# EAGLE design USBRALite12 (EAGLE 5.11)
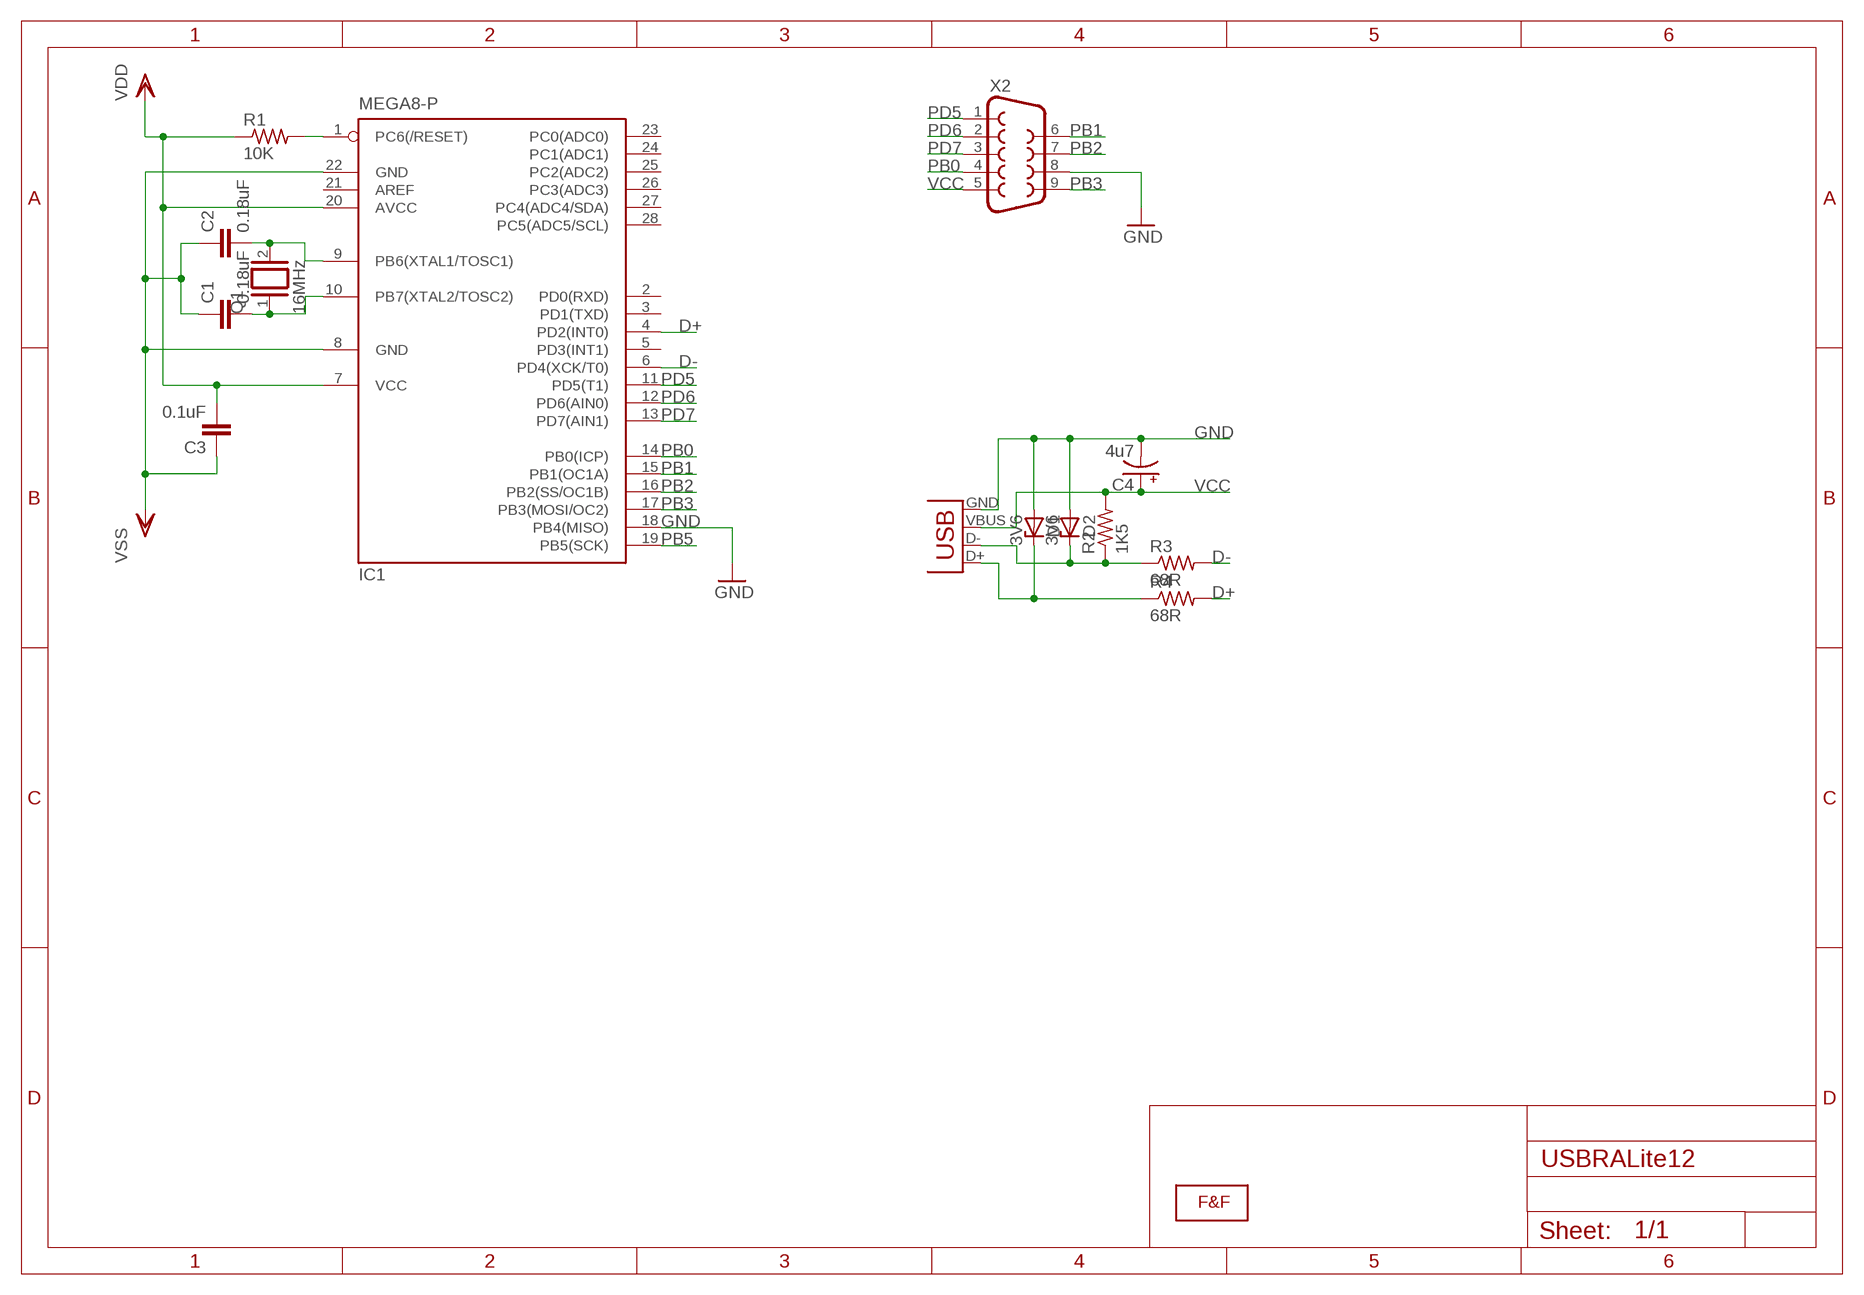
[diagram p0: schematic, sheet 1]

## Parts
C1  0.18uF  CAPPTH  [CAP-PTH-SMALL]
C2  0.18uF  CAPPTH  [CAP-PTH-SMALL]
C3  0.1uF  CAPPTH  [CAP-PTH-SMALL]
C4  4u7  CPOL-USE2.5-6  [E2,5-6]
D1  3V6  ZENER-DIODEZD-5  [ZDIO-5]
D2  3V6  ZENER-DIODEZD-5  [ZDIO-5]
IC1  MEGA8-P  [DIL28-3]
Q1  16MHz  XTAL/S  [QS]
R1  10K  R-US_0207/10  [0207/10]
R2  1K5  R-US_0207/10  [0207/10]
R3  68R  R-US_0207/10  [0207/10]
R4  68R  R-US_0207/10  [0207/10]
U$1  LOGOLOGO_WITH_SMOKE_BIG  [LOGO_BIG]
X1  USBPTH  [USB-B-PTH]
X2  DB9MALE  [DB9_MALE]

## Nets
D+: IC1.4(PD2(INT0)) R4.2
D-: IC1.6(PD4(XCK/T0)) R3.2
GND: C1.1 C2.1 C3.1 C4.- D1.A D2.A IC1.8(GND) IC1.18(PB4(MISO)) IC1.22(GND) X1.GND X2.8 ; supply symbol labelled VSS
N$1: IC1.1(PC6(/RESET)) R1.2
N$2: C2.2 IC1.9(PB6(XTAL1/TOSC1)) Q1.2
N$3: C1.2 IC1.10(PB7(XTAL2/TOSC2)) Q1.1
N$8: D1.C R4.1 X1.D+
N$9: D2.C R2.1 R3.1 X1.D-
PB0: IC1.14(PB0(ICP)) X2.4
PB1: IC1.15(PB1(OC1A)) X2.6
PB2: IC1.16(PB2(SS/OC1B)) X2.7
PB3: IC1.17(PB3(MOSI/OC2)) X2.9
PB5: IC1.19(PB5(SCK))
PD5: IC1.11(PD5(T1)) X2.1
PD6: IC1.12(PD6(AIN0)) X2.2
PD7: IC1.13(PD7(AIN1)) X2.3
VCC: C3.2 C4.+ IC1.7(VCC) IC1.20(AVCC) R1.1 R2.2 X1.VBUS X2.5 ; supply symbol labelled VDD
Unconnected: IC1.2(PD0(RXD)) IC1.3(PD1(TXD)) IC1.5(PD3(INT1)) IC1.21(AREF) IC1.23(PC0(ADC0)) IC1.24(PC1(ADC1)) IC1.25(PC2(ADC2)) IC1.26(PC3(ADC3)) IC1.27(PC4(ADC4/SDA)) IC1.28(PC5(ADC5/SCL))

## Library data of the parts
C1-C3 = SparkFun:CAP: Capacitor
C4 = adafruit:CPOL-US: POLARIZED CAPACITOR, American symbol
D1 D2 = diode:ZENER-DIODE: Z-Diode
IC1 = atmel:MEGA8-P: MICROCONTROLLER 8 Kbytes FLASH, 1 kbytes SRAM, 512 bytes EEPROM, USART, 4-channel 10 bit ADC, 2-channel 8 bit ADC Pin compatible with Atmega48, ATMega88, ATMega168 Source: avr.lbr; OC_FARNELL: unknown; OC_NEWARK: unknown
Q1 = special:XTAL/S: CRYSTAL
R1-R4 = adafruit:R-US_: RESISTOR, American symbol
U$1 = F&F:LOGO: Faísca e Fumaça Logo
X1 = SparkFun:USB: USB Connectors USB-B-PTH is fully proven SKU : PRT-00139 USB-miniB is fully proven SKU : PRT-00587 USB-A-PCB is untested. USB-A-H is throughly reviewed, but untested. Spark Fun Electronics SKU : PRT-00437 USB-B-SMT is throughly reviewed, but untested. Needs silkscreen touching up. USB-A-S has not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
X2 = SparkFun:DB9: DB9 Connector Standard DB9 (D-Sub 9) serial connector. Can be used for CAN bus as well as RS485 and RS232. Footprint production proven. Spark Fun Electronics SKU : PRT-00429

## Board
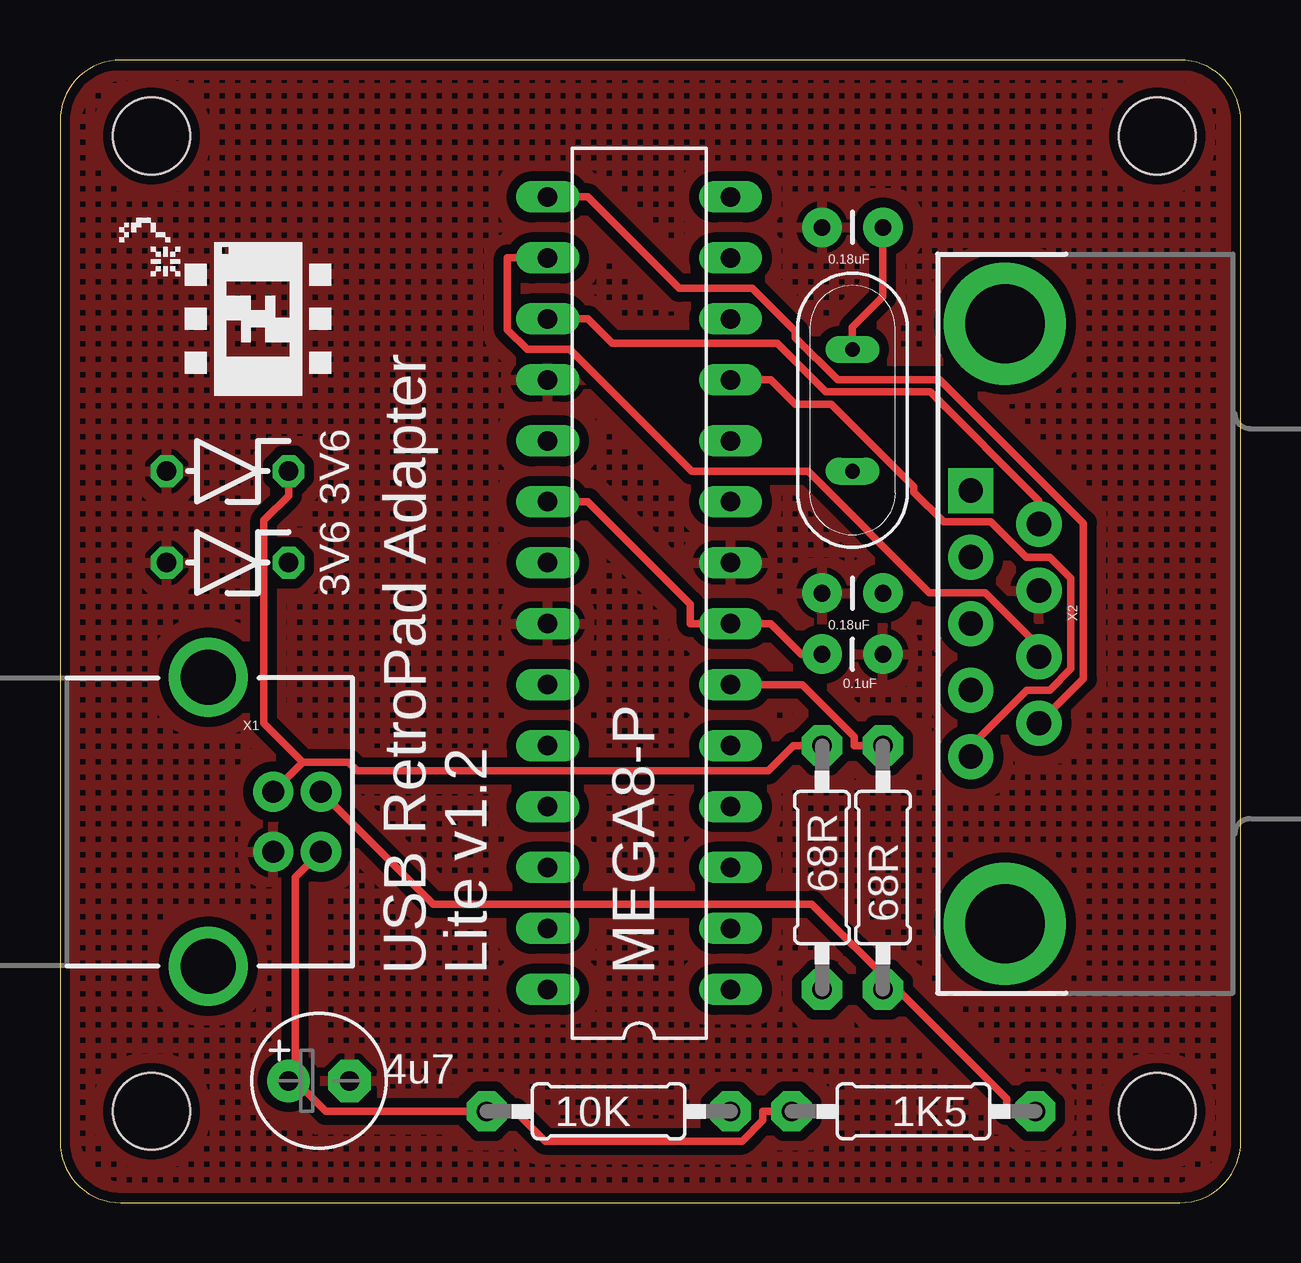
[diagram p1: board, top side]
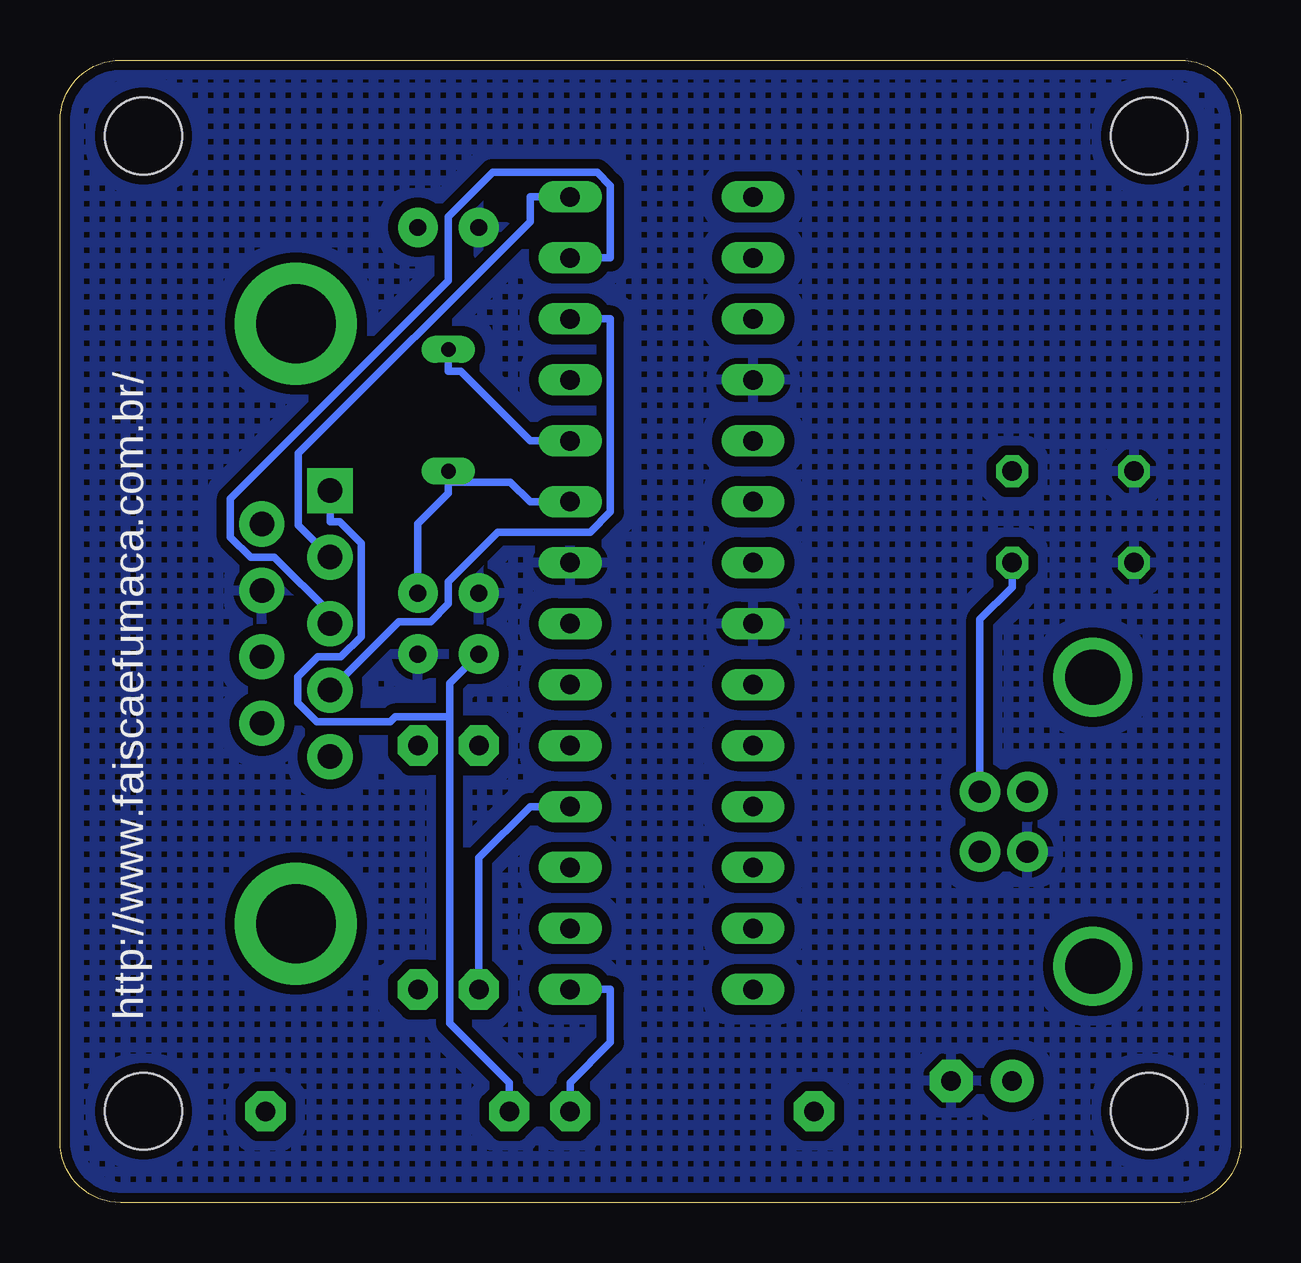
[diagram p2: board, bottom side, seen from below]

Size 49.2 x 47.62 mm. Coordinates in mm from the lower left corner, seen from the top.
Outline: 49.2,45.08 arc90 46.66,47.62 2.54,47.62 arc90 0,45.08 0,2.54 arc90 2.54,0 46.66,0 arc90 49.2,2.54 49.2,45.08
Copper layers (1*16): Top 0.035mm / dielectric 1.5mm / Bottom 0.035mm
Design rules "ITead_rule": minimum track width 6mil, minimum drill 12mil, track to track 6mil, track to pad 6mil, pad to pad 6mil, via to via 6mil, smd to smd 0mil, copper to edge 10mil, drill to drill 10mil, minimum pad ring 10mil, minimum via ring 6mil, stop-mask expansion 2mil, vias tented up to drill 100mil, thermal gap 10mil
Holes 3.2 mm at 3.81,44.45 3.81,3.81 45.72,44.45 45.72,3.81

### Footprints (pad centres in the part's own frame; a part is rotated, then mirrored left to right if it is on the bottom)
CAP-PTH-SMALL = drill 0.7 pad 1.651 round: 1 0,0; 2 2.54,0
E2,5-6 = drill 0.813 pad 1.778 round: + -1.27,0 | drill 0.813 pad 1.778 octagon: - 1.27,0
ZDIO-5 = drill 0.813 octagon: A 2.54,0; C -2.54,0
DIL28-3 = drill 0.813 long: 1 -16.51,-3.81; 2 -13.97,-3.81; 3 -11.43,-3.81; 4 -8.89,-3.81; 5 -6.35,-3.81; 6 -3.81,-3.81; 7 -1.27,-3.81; 8 1.27,-3.81; 9 3.81,-3.81; 10 6.35,-3.81; 11 8.89,-3.81; 12 11.43,-3.81; 13 13.97,-3.81; 14 16.51,-3.81; 15 16.51,3.81; 16 13.97,3.81; 17 11.43,3.81; 18 8.89,3.81; 19 6.35,3.81; 20 3.81,3.81; 21 1.27,3.81; 22 -1.27,3.81; 23 -3.81,3.81; 24 -6.35,3.81; 25 -8.89,3.81; 26 -11.43,3.81; 27 -13.97,3.81; 28 -16.51,3.81
QS = drill 0.61 long: 1 -2.54,0; 2 2.54,0
0207/10 = drill 0.813 pad 1.676 octagon: 1 -5.08,0; 2 5.08,0
USB-B-PTH = drill 0.914 pad 1.676 round: D+ 0,1.25; D- 1.981,1.25; GND 0,-1.25; VBUS 1.981,-1.25 | drill 2.286 round: S1 -2.718,-6.02; S2 -2.718,6.02
DB9_MALE = drill 1.016 pad 1.88 round: 1 5.54,-1.42; 2 2.77,-1.42; 3 0,-1.42; 4 -2.77,-1.42; 6 4.15,1.42; 7 1.38,1.42; 8 -1.38,1.42; 9 -4.15,1.42 | drill 1.016 pad 1.88 square: 5 -5.54,-1.42 | drill 3.302 pad 5.08 round: G1 -12.5,0; G2 12.5,0

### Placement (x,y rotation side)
C1  31.75,40.64 0 top
C2  31.75,25.4 0 top
C3  34.29,22.86 180 top
C4  10.79,5.08 0 top
D1  6.99,30.48 180 top
D2  6.99,26.67 180 top
IC1  24.13,25.4 90 top
Q1  33.02,33.02 270 top
R1  22.86,3.81 0 top
R2  35.56,3.81 180 top
R3  34.29,13.97 90 top
R4  31.75,13.97 270 top
U$1  8.26,36.83 90 top
X1  8.89,15.88 0 top
X2  39.37,24.13 270 top

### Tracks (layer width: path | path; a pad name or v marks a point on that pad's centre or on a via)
D+
  Bottom 0.305: IC1.4 29.62,16.51 31.75,14.38 R4.2
D-
  Top 0.305: R3.2 33.1,19.05 33.1,19.42 30.93,21.59 IC1.6
GND
  pour Bottom (isolate 0.406, hatched): 0,46.99 49.53,46.99 49.53,0 0,0
  pour Top (isolate 0.406, hatched): 0,46.99 49.53,46.99 49.53,0 0,0
N$1
  Bottom 0.305: R1.2 27.94,5 26.26,6.68 26.26,8.89 IC1.1
N$2
  Bottom 0.305: IC1.9 29.62,29.21 30.43,30.02 33.02,30.02 | 33.02,30.02 33.02,29.57 34.29,28.3 C2.2 | 33.02,30.02 Q1.2
N$3
  Top 0.305: Q1.1 33.02,36.47 34.29,37.74 C1.2
  Bottom 0.305: IC1.10 29.62,31.75 32.51,34.65 33.02,34.65 Q1.1
N$8
  Top 0.305: 10.12,18.35 12.02,18.35 12.38,17.99 29.5,17.99 30.56,19.05 R4.1 | X1.D+ 10.12,18.35 | 10.12,18.35 8.49,19.98 8.49,28.43 9.53,29.46 D1.C
N$9
  Top 0.305: R2.1 39.45,3.81 39.45,4.33 34.89,8.89 | X1.D- 15.55,12.45 31.33,12.45 34.89,8.89 | 34.89,8.89 R3.1
  Bottom 0.305: D2.C 9.53,25.65 10.87,24.31 X1.D-
PB0
  Bottom 0.305: IC1.14 29.62,41.91 29.62,40.88 39.27,31.23 39.27,28.22 X2.4
PB1
  Top 0.305: IC1.15 22,41.91 25.81,38.1 28.84,38.1 30.64,36.3 30.64,36.05 32.4,34.29 36.66,34.29 42.64,28.31 42.64,21.83 X2.6
PB2
  Top 0.305: IC1.16 18.64,39.37 18.64,36.38 19.46,35.56 21.23,35.56 26.31,30.48 31.17,30.48 36.22,25.43 38.55,25.43 40.79,23.18 X2.7
PB3
  Top 0.305: IC1.17 22,36.83 23.01,35.81 29.88,35.81 31.91,33.78 36.26,33.78 40.79,29.25 X2.9
PD5
  Top 0.305: IC1.11 29.62,34.29 30.63,33.27 32.14,33.27 35.57,29.84 35.57,29.61 36.81,28.37 38.78,28.37 40.26,26.89 41.24,26.89 42.12,26.01 42.12,22.25 41.24,21.36 40.29,21.36 37.95,19.02 X2.1
PD6
  Bottom 0.305: IC1.12 26.26,36.83 26.26,28.79 27.11,27.94 30.95,27.94 33.02,25.87 33.02,24.96 33.76,24.22 35.09,24.22 X2.2
PD7
  Bottom 0.305: IC1.13 26.26,39.37 26.26,42.38 26.82,42.93 31.17,42.93 33.02,41.08 33.02,38.42 42.1,29.34 42.1,27.73 41.26,26.89 40.26,26.89 37.95,24.58 X2.3
VCC
  Top 0.305: 9.81,5.08 9.81,13.56 X1.VBUS | 9.81,5.08 11.08,3.81 R1.1 18.97,3.81 20.21,2.57 28.42,2.57 29.29,3.44 29.29,3.81 R2.2 | C4.+ 9.81,5.08 | C3.2 30.89,22.86 29.62,24.13 IC1.7 26.26,24.13 26.26,24.94 22,29.21 IC1.20
  Bottom 0.305: X2.5 37.95,28.38 37.55,28.38 36.65,27.48 36.65,23.59 37.5,22.75 38.46,22.75 39.29,21.92 39.29,20.84 38.5,20.04 35.44,20.04 35.24,20.24 32.97,20.24 | 32.97,20.24 32.97,21.64 C3.2 | 32.97,20.24 32.97,7.49 30.48,5 R2.2

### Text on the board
tPlace: USB RetroPad Adapter | Lite v1.2
bPlace: http://www.faiscaefumaca.com.br/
